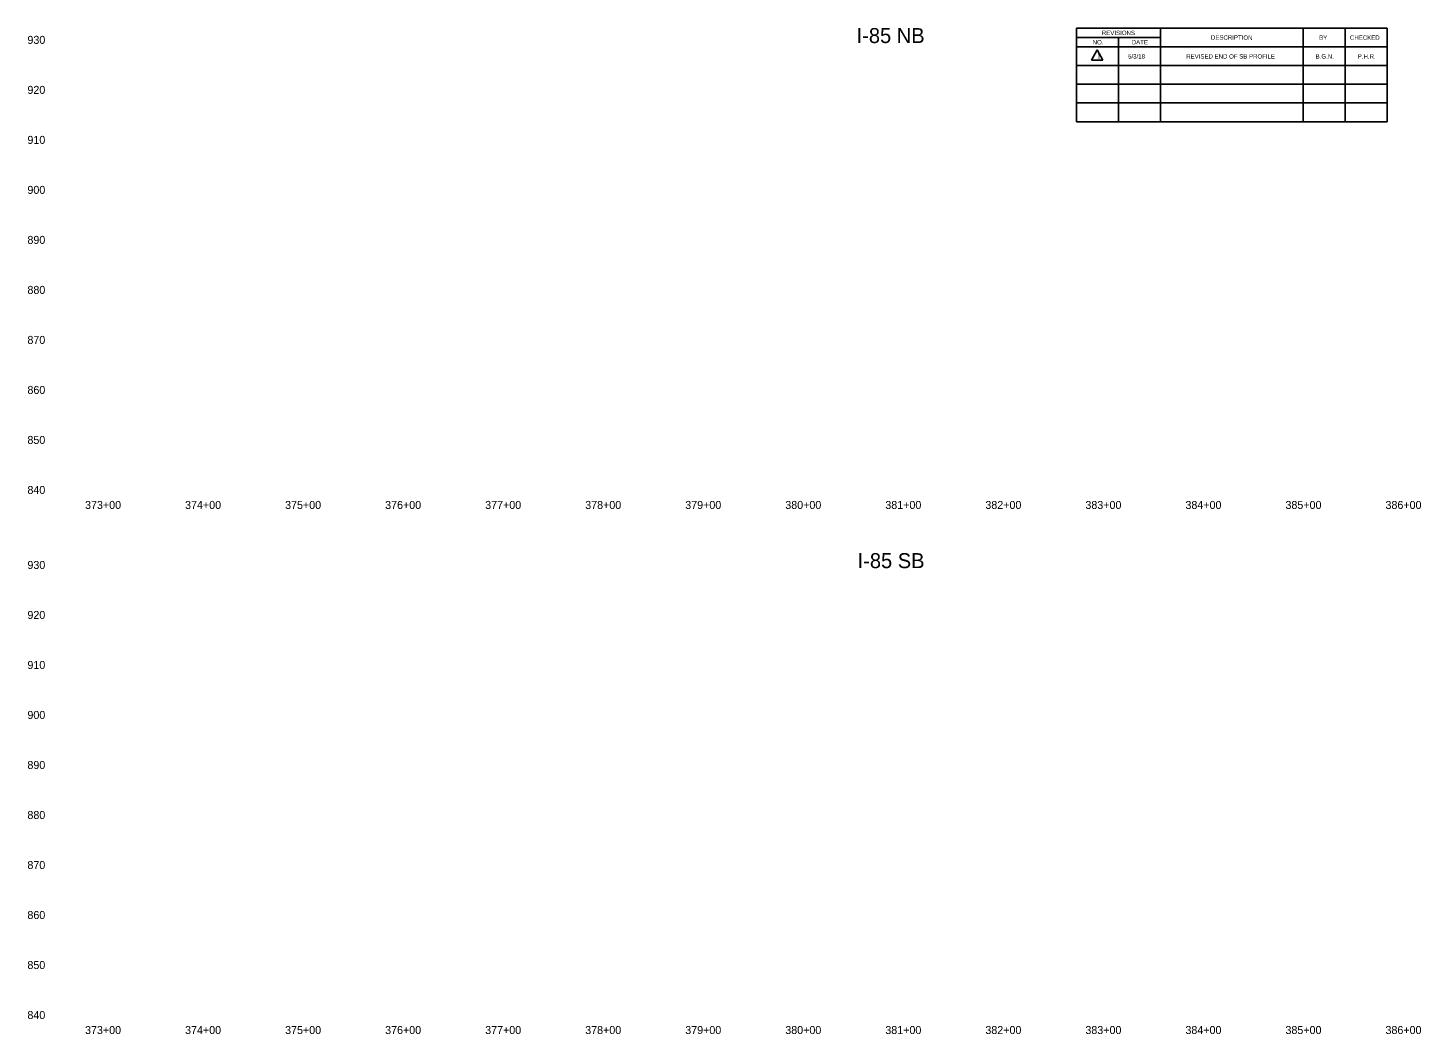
# Model space of a CAD drawing. Extents: x 16989642 to 16992537, y 12627871 to 12628898.
# Drawn here: x 16989642 to 16991034, y 12627871 to 12628878 of the extents above; entities that cross this region are included whole.
import ezdxf

# ---------------------------------------------------------------- set-up
doc = ezdxf.new("R2010")
doc.units = 0
doc.layers.add('Default', color=7, linetype='Continuous')
doc.layers.add('RD_SHT_TX', color=7, linetype='Continuous')

msp = doc.modelspace()

# ---------------------------------------------------------------- linework, layer by layer
at = {"layer": 'RD_SHT_TX'}
for p, q in [((16990867.3, 12628877.2), (16990690, 12628877.3)), ((16990690, 12628877.3), (16990690, 12628783.8)), ((16990690, 12628877.2), (16991000.6, 12628877.2)), ((16990774, 12628867.9), (16990690, 12628867.9)), ((16990732, 12628783.8), (16990732, 12628867.9)), ((16990774, 12628783.8), (16990774, 12628877.2)), ((16990916.6, 12628783.8), (16990916.6, 12628877.2)), ((16990958.6, 12628783.8), (16990958.6, 12628877.2)), ((16991000.6, 12628783.7), (16991000.6, 12628877.2)), ((16991000.6, 12628858.6), (16990690, 12628858.6)), ((16990710.7, 12628855.6), (16990705, 12628845.4)), ((16990710.7, 12628855.6), (16990716.4, 12628845.4)), ((16991000.6, 12628839.9), (16990690, 12628839.9)), ((16990705, 12628845.4), (16990716.4, 12628845.4)), ((16991000.6, 12628821.2), (16990690, 12628821.2)), ((16991000.6, 12628802.5), (16990690, 12628802.5)), ((16991000.6, 12628783.7), (16990690, 12628783.8))]:
    msp.add_line(p, q, dxfattribs=at)

# ---------------------------------------------------------------- texts
at = {"layer": 'Default'}
for s, p in [('930', (16989641.2, 12628861.6)), ('920', (16989641.2, 12628811.6)), ('910', (16989641.2, 12628761.6)), ('900', (16989641.2, 12628711.6)), ('890', (16989641.2, 12628661.6)), ('880', (16989641.2, 12628611.6)), ('870', (16989641.2, 12628561.6)), ('860', (16989641.2, 12628511.6)), ('850', (16989641.2, 12628461.6)), ('840', (16989641.2, 12628411.6)), ('373+00', (16989698.8, 12628396.6)), ('374+00', (16989798.8, 12628396.6)), ('375+00', (16989898.8, 12628396.6)), ('376+00', (16989998.8, 12628396.6)), ('377+00', (16990098.8, 12628396.6)), ('378+00', (16990198.8, 12628396.6)), ('379+00', (16990298.8, 12628396.6)), ('380+00', (16990398.8, 12628396.6)), ('381+00', (16990498.8, 12628396.6)), ('382+00', (16990598.8, 12628396.6)), ('383+00', (16990698.8, 12628396.6)), ('384+00', (16990798.8, 12628396.6)), ('385+00', (16990898.8, 12628396.6)), ('386+00', (16990998.8, 12628396.6)), ('930', (16989641.2, 12628336.6)), ('920', (16989641.2, 12628286.6)), ('910', (16989641.2, 12628236.6)), ('900', (16989641.2, 12628186.6)), ('890', (16989641.2, 12628136.6)), ('880', (16989641.2, 12628086.6)), ('870', (16989641.2, 12628036.6)), ('860', (16989641.2, 12627986.6)), ('850', (16989641.2, 12627936.6)), ('840', (16989641.2, 12627886.6)), ('373+00', (16989698.8, 12627871.6)), ('374+00', (16989798.8, 12627871.6)), ('375+00', (16989898.8, 12627871.6)), ('376+00', (16989998.8, 12627871.6)), ('377+00', (16990098.8, 12627871.6)), ('378+00', (16990198.8, 12627871.6)), ('379+00', (16990298.8, 12627871.6)), ('380+00', (16990398.8, 12627871.6)), ('381+00', (16990498.8, 12627871.6)), ('382+00', (16990598.8, 12627871.6)), ('383+00', (16990698.8, 12627871.6)), ('384+00', (16990798.8, 12627871.6)), ('385+00', (16990898.8, 12627871.6)), ('386+00', (16990998.8, 12627871.6))]:
    msp.add_text(s, height=8, dxfattribs=at).set_placement(p)
at = {"layer": 'RD_SHT_TX'}
for s, height, p in [('I-85 NB', 15, (16990470.1, 12628862.4)), ('NO.', 4.4, (16990706.1, 12628861)), ('REVISIONS', 4.4, (16990715.3, 12628870.4)), ('CHECKED', 4.4, (16990963.3, 12628865.7)), ('1', 4.4, (16990710.7, 12628847.1)), ('5/3/18', 4.4, (16990741.5, 12628846.9)), ('REVISED END OF SB PROFILE', 4.4, (16990799.6, 12628846.9)), ('B.G.N.', 4.4, (16990928.9, 12628846.9)), ('P.H.R.', 4.4, (16990971.1, 12628846.9)), ('I-85 SB', 15, (16990471.1, 12628337.4))]:
    msp.add_text(s, height=height, dxfattribs=at).set_placement(p)
for s, height, p in [('DATE', 4.41, (16990745.1, 12628861.1)), ('DESCRIPTION', 4.408, (16990824.3, 12628865.8)), ('BY', 4.41, (16990932.4, 12628865.7))]:
    msp.add_text(s, height=height, rotation=359.7246, dxfattribs=at).set_placement(p)

doc.saveas('drawing.dxf')
